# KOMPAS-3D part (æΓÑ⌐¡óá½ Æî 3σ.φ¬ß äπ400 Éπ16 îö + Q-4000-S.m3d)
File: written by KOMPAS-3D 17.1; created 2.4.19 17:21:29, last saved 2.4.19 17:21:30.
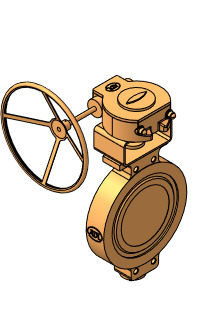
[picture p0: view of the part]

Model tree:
1. Операция без истории:1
